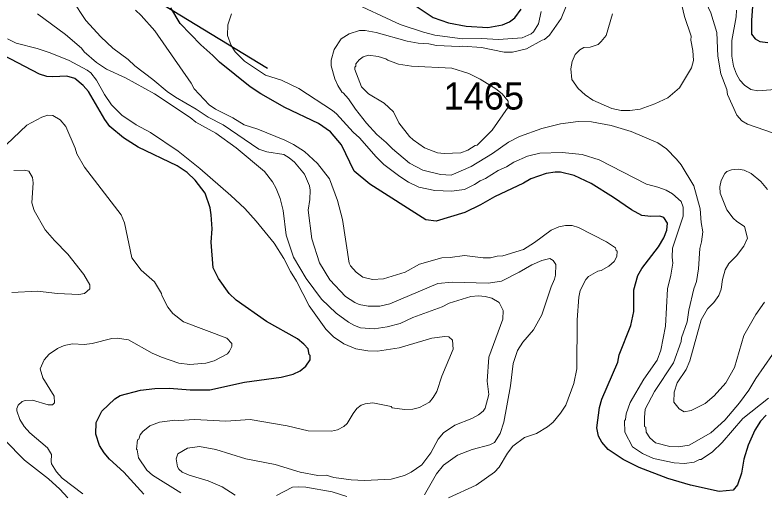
# Model space of a CAD drawing. Extents: x 598.3 to 623.2, y 6902.2 to 6930.1.
# Drawn here: x 600.922 to 603.134, y 6910.701 to 6912.11 of the extents above; entities that cross this region are included whole.
import ezdxf

# ---------------------------------------------------------------- set-up
doc = ezdxf.new("R2010")
doc.units = 0
doc.header["$LTSCALE"] = 0.032
for name, color, linetype, lineweight in [('1', 7, 'Continuous', 25), ('2', 7, 'Continuous', 13), ('26', 7, 'Continuous', 25)]:
    doc.layers.add(name, color=color, linetype=linetype, lineweight=lineweight)
doc.layers.add('21', color=7, linetype='Continuous')

msp = doc.modelspace()

# ---------------------------------------------------------------- linework, layer by layer
at = {"layer": '1'}
for points in [[(603.1021, 6912.1642), (603.0971, 6912.0933), (603.0969, 6912.0536), (603.1081, 6912.0394), (603.1219, 6912.0314), (603.145, 6912.0283)], [(602.1071, 6912.1361), (602.1574, 6912.1028), (602.202, 6912.0865), (602.2546, 6912.0774), (602.3188, 6912.0728), (602.3613, 6912.0811), (602.382, 6912.0899), (602.3984, 6912.1017), (602.4173, 6912.1272)], [(601.4101, 6912.085), (601.3825, 6912.1309)], [(603.1408, 6910.9279), (603.1241, 6910.9102), (603.1069, 6910.8834), (603.0874, 6910.8396), (603.0747, 6910.7981), (603.0675, 6910.7564), (603.056, 6910.7225), (603.0429, 6910.7063), (603.0015, 6910.7023), (602.9173, 6910.7209), (602.8505, 6910.7406), (602.7656, 6910.7733), (602.7178, 6910.7973), (602.6737, 6910.8264), (602.6552, 6910.8482), (602.6452, 6910.8665), (602.6408, 6910.8907), (602.6481, 6910.9506), (602.6552, 6910.9755), (602.7023, 6911.0846), (602.7066, 6911.1061), (602.7412, 6911.1931), (602.7492, 6911.2346), (602.7493, 6911.2983), (602.7615, 6911.3404), (602.7729, 6911.3615), (602.8223, 6911.4252), (602.8383, 6911.4521), (602.8471, 6911.4745), (602.8486, 6911.4955), (602.8379, 6911.5118), (602.8261, 6911.5158), (602.8001, 6911.515), (602.7732, 6911.5179), (602.7424, 6911.5344), (602.6894, 6911.5713), (602.6237, 6911.6125), (602.5736, 6911.6359), (602.5326, 6911.6461), (602.5177, 6911.6462), (602.4905, 6911.6421), (602.4451, 6911.626), (602.4236, 6911.6136), (602.3383, 6911.5734), (602.2968, 6911.5494), (602.2508, 6911.5266), (602.1655, 6911.5014), (602.1348, 6911.5053), (601.9703, 6911.6099), (601.9234, 6911.6488), (601.8857, 6911.7268), (601.8537, 6911.7653), (601.818, 6911.7896), (601.7187, 6911.8363), (601.6475, 6911.8769), (601.616, 6911.8983), (601.5259, 6911.9702), (601.506, 6911.9907), (601.4705, 6912.0215), (601.4101, 6912.085)], [(601.5074, 6911.3632), (601.501, 6911.4386), (601.5042, 6911.478), (601.5017, 6911.5201), (601.4979, 6911.5402), (601.4831, 6911.5833), (601.4542, 6911.6217), (601.43, 6911.6451), (601.4011, 6911.6649), (601.2859, 6911.7197), (601.2425, 6911.7467), (601.2017, 6911.7803), (601.1869, 6911.8015), (601.1385, 6911.8839), (601.1227, 6911.9021), (601.0981, 6911.9227), (601.0752, 6911.9294), (601.0338, 6911.9272), (601.0156, 6911.9286), (600.9945, 6911.935), (600.8872, 6911.9911)], [(601.3022, 6910.6944), (601.2433, 6910.7599), (601.2011, 6910.7981), (601.1848, 6910.817), (601.1717, 6910.838), (601.161, 6910.8716), (601.1611, 6910.9062), (601.1787, 6910.9399), (601.2162, 6910.9761), (601.2325, 6910.9857), (601.2928, 6911.0019), (601.3349, 6911.0067), (601.3777, 6911.0074), (601.4388, 6911.0031), (601.4974, 6911.0025), (601.5994, 6911.0252), (601.7082, 6911.0402), (601.7431, 6911.0493), (601.7637, 6911.0591), (601.7804, 6911.0725), (601.7932, 6911.0911), (601.794, 6911.1039), (601.7907, 6911.1068), (601.7875, 6911.1238), (601.7752, 6911.1379), (601.7564, 6911.1533), (601.6651, 6911.2051), (601.5754, 6911.2681), (601.5547, 6911.2874), (601.5228, 6911.332), (601.5074, 6911.3632)]]:
    msp.add_lwpolyline(points, dxfattribs=at)
at = {"layer": '2'}
for points in [[(603.1877, 6911.7517), (603.0854, 6911.7872), (603.0683, 6911.7972), (603.0538, 6911.8145), (603.0261, 6911.8755), (603.0245, 6911.8904), (603.0066, 6911.9359), (602.9976, 6911.9887), (602.9952, 6912.0587), (602.9772, 6912.1162), (602.9552, 6912.1633), (602.9523, 6912.1837), (602.9377, 6912.226), (602.925, 6912.2514), (602.9032, 6912.2809), (602.8854, 6912.3113), (602.8346, 6912.3743), (602.7973, 6912.427)], [(602.0294, 6911.2572), (601.999, 6911.2497), (601.9651, 6911.2495), (601.9387, 6911.2553), (601.9254, 6911.2606), (601.8984, 6911.2786), (601.8522, 6911.328), (601.8215, 6911.3777), (601.7989, 6911.4484), (601.7876, 6911.5331), (601.7923, 6911.565), (601.7933, 6911.5927), (601.7915, 6911.6059), (601.7772, 6911.6394), (601.7472, 6911.675), (601.7312, 6911.6886), (601.7157, 6911.6981), (601.6655, 6911.7058), (601.6421, 6911.714), (601.5369, 6911.786), (601.4919, 6911.8085), (601.4573, 6911.8322), (601.3958, 6911.8672), (601.3711, 6911.8844), (601.3292, 6911.9199), (601.2757, 6911.9603), (601.2556, 6911.9788), (601.211, 6912.0122), (601.1749, 6912.0458), (601.1306, 6912.0941), (601.0905, 6912.1561)], [(602.55, 6912.1356), (602.5354, 6912.0992), (602.501, 6912.0505), (602.4854, 6912.0376), (602.4786, 6912.0361), (602.4322, 6912.0104), (602.3917, 6912.0007), (602.3666, 6912.0007), (602.2994, 6912.0136), (602.2431, 6912.0183), (602.2335, 6912.0169), (602.1671, 6912.0201), (602.144, 6912.0249), (602.1122, 6912.0272), (602.0798, 6912.0328), (601.9886, 6912.0581), (601.9559, 6912.0638), (601.9393, 6912.0638), (601.9086, 6912.0543), (601.8855, 6912.0393), (601.8643, 6912.0083), (601.8556, 6911.9767), (601.8556, 6911.96), (601.8662, 6911.9214), (601.8751, 6911.9017), (601.8883, 6911.8807), (601.8914, 6911.8797), (601.9065, 6911.8622), (601.9271, 6911.8319), (601.9598, 6911.7904), (601.9907, 6911.7571), (602.018, 6911.7337), (602.0366, 6911.7143), (602.087, 6911.6719), (602.1261, 6911.6516), (602.1788, 6911.6389), (602.2105, 6911.6374), (602.2695, 6911.6629), (602.3326, 6911.7008), (602.3792, 6911.7343), (602.4117, 6911.7509), (602.4775, 6911.7749), (602.5326, 6911.7886), (602.5855, 6911.7958), (602.6248, 6911.7942), (602.6826, 6911.7838), (602.7418, 6911.7663), (602.8207, 6911.7326), (602.8465, 6911.7148), (602.8761, 6911.6843), (602.8891, 6911.6674), (602.9271, 6911.6059), (602.9451, 6911.5376), (602.9483, 6911.4972), (602.9531, 6911.4694), (602.9499, 6911.4405), (602.945, 6911.4202), (602.9411, 6911.3601), (602.9346, 6911.3226), (602.9266, 6911.3007), (602.912, 6911.2384), (602.907, 6911.2042), (602.8902, 6911.1562), (602.8899, 6911.1456), (602.8666, 6911.083)], [(601.9071, 6912.1529), (602.0598, 6912.0815), (602.1281, 6912.0588), (602.1615, 6912.0509), (602.2436, 6912.0396), (602.2997, 6912.0403), (602.3503, 6912.0379), (602.4196, 6912.0425), (602.4462, 6912.0539), (602.4533, 6912.0601), (602.4676, 6912.0838), (602.4756, 6912.1205)], [(602.8886, 6912.1523), (602.8993, 6912.1058), (602.9191, 6912.0476), (602.9184, 6912.0361), (602.924, 6912.0055), (602.9263, 6911.9759), (602.9195, 6911.9543), (602.885, 6911.8952), (602.8502, 6911.8653), (602.8114, 6911.8472), (602.7686, 6911.8315), (602.7383, 6911.8276), (602.7123, 6911.8282), (602.6843, 6911.8343), (602.6289, 6911.8585), (602.6062, 6911.8739), (602.5851, 6911.8928), (602.5663, 6911.9199), (602.5639, 6911.9511), (602.567, 6911.9728), (602.5766, 6911.9935), (602.5898, 6912.0071), (602.6022, 6912.0136), (602.6204, 6912.015), (602.6438, 6912.0232), (602.6536, 6912.0314), (602.6681, 6912.049), (602.6868, 6912.1134)], [(601.9537, 6910.7347), (602.0327, 6910.7393), (602.0723, 6910.75), (602.0924, 6910.76), (602.1235, 6910.7817), (602.1503, 6910.8167), (602.1719, 6910.8575), (602.187, 6910.8759), (602.2208, 6910.899), (602.2713, 6910.9183), (602.2908, 6910.9288), (602.3042, 6910.9396), (602.3104, 6910.9492), (602.3209, 6910.9888), (602.3169, 6911.0282), (602.3209, 6911.0995), (602.3631, 6911.2112), (602.3638, 6911.237), (602.352, 6911.2605), (602.3305, 6911.2734), (602.3105, 6911.2786), (602.2906, 6911.2803), (602.2685, 6911.2786), (602.2046, 6911.2587), (602.184, 6911.2477), (602.0967, 6911.217), (602.0593, 6911.1991), (602.0214, 6911.1893), (601.9824, 6911.1831), (601.9427, 6911.1864), (601.9241, 6911.1926), (601.9064, 6911.2026), (601.8706, 6911.229), (601.8274, 6911.2703), (601.7814, 6911.3315), (601.7448, 6911.395), (601.7228, 6911.4597), (601.7139, 6911.5323), (601.705, 6911.5682), (601.6935, 6911.5978), (601.6825, 6911.6168), (601.659, 6911.6475), (601.5748, 6911.718), (601.515, 6911.7609), (601.4561, 6911.7939), (601.4392, 6911.8074), (601.3342, 6911.8768), (601.2479, 6911.9244), (601.1922, 6911.9502), (601.1621, 6911.9695), (601.1261, 6912.0016), (601.1178, 6912.0122), (601.0709, 6912.0526), (600.9883, 6912.1136)], [(602.2018, 6910.6843), (602.2843, 6910.7215), (602.3384, 6910.7593), (602.3519, 6910.7743), (602.3767, 6910.8154), (602.3925, 6910.8368), (602.4268, 6910.8624), (602.4624, 6910.8737), (602.4946, 6910.8938), (602.5116, 6910.9075), (602.5329, 6910.9336), (602.5483, 6910.9578), (602.5721, 6911.0218), (602.5808, 6911.0649), (602.5825, 6911.2099), (602.5872, 6911.2761), (602.5912, 6911.2959), (602.608, 6911.329), (602.6155, 6911.3376), (602.6436, 6911.3532), (602.6536, 6911.3556), (602.6756, 6911.3686), (602.692, 6911.3817), (602.699, 6911.3966), (602.7006, 6911.4127), (602.6974, 6911.4148), (602.6952, 6911.4223), (602.6685, 6911.4404), (602.586, 6911.4824), (602.5679, 6911.4882), (602.5482, 6911.4882), (602.5281, 6911.484), (602.5052, 6911.4748), (602.4558, 6911.4377), (602.4233, 6911.4176), (602.3626, 6911.3985), (602.3459, 6911.3976), (602.3263, 6911.3931), (602.3051, 6911.3928), (602.2493, 6911.4001), (602.2074, 6911.3936), (602.1824, 6911.3927), (602.1163, 6911.3741), (602.0738, 6911.3506), (602.0106, 6911.3312), (601.9781, 6911.3288), (601.9489, 6911.3355), (601.9299, 6911.35), (601.9132, 6911.369), (601.9093, 6911.3766), (601.8895, 6911.5061), (601.8742, 6911.5617), (601.8503, 6911.6257), (601.8154, 6911.6717), (601.777, 6911.707), (601.7441, 6911.7277), (601.7187, 6911.7404), (601.6395, 6911.7729), (601.5986, 6911.7859), (601.5652, 6911.8058), (601.514, 6911.8316), (601.4953, 6911.8444), (601.4513, 6911.8915), (601.4423, 6911.909), (601.3346, 6912.0634), (601.2947, 6912.1081), (601.2773, 6912.1239)], [(602.7867, 6911.6103), (602.647, 6911.6826), (602.5968, 6911.698), (602.5377, 6911.7043), (602.4724, 6911.7019), (602.4351, 6911.693), (602.3951, 6911.6755), (602.3737, 6911.6617), (602.3491, 6911.6508), (602.3119, 6911.6274), (602.2957, 6911.6201), (602.2793, 6911.6089), (602.2492, 6911.5944), (602.2107, 6911.5895), (602.1618, 6911.5918), (602.1143, 6911.6011), (602.0841, 6911.616), (602.058, 6911.6325), (602.0117, 6911.6683), (601.989, 6911.6906), (601.9393, 6911.747), (601.9202, 6911.7636), (601.8711, 6911.8183), (601.8598, 6911.8281), (601.7603, 6911.8929), (601.7091, 6911.9178), (601.6618, 6911.9324), (601.5994, 6911.9735), (601.5721, 6912.0009), (601.5602, 6912.0202), (601.5496, 6912.0492), (601.5502, 6912.0807), (601.5609, 6912.1139)], [(603.0527, 6912.124), (603.052, 6912.1046), (603.0391, 6912.0351), (603.0391, 6911.9888), (603.0442, 6911.9593), (603.0533, 6911.9348), (603.0628, 6911.9177)], [(600.8993, 6912.0392), (600.925, 6912.0265), (600.9872, 6912.0114), (601.0257, 6911.9986), (601.0822, 6911.9753), (601.1349, 6911.9466), (601.1453, 6911.9387), (601.1628, 6911.9179), (601.1863, 6911.8753), (601.2065, 6911.845), (601.2369, 6911.8138), (601.2795, 6911.786), (601.3216, 6911.7634), (601.4036, 6911.7078), (601.4675, 6911.657), (601.5597, 6911.5769), (601.6004, 6911.5385), (601.6344, 6911.5015), (601.6871, 6911.4364), (601.7162, 6911.3906), (601.7353, 6911.3527), (601.7534, 6911.3242), (601.7906, 6911.2514), (601.8399, 6911.1817), (601.8624, 6911.1596), (601.8931, 6911.1392), (601.9286, 6911.1243), (601.9638, 6911.1177), (601.9922, 6911.1168), (602.0566, 6911.1265), (602.1529, 6911.1557), (602.1918, 6911.1604), (602.2033, 6911.1596), (602.2141, 6911.1495), (602.2164, 6911.123), (602.1828, 6911.0428)], [(603.0628, 6911.9177), (603.0768, 6911.9029), (603.095, 6911.8898), (603.1158, 6911.8858), (603.1669, 6911.8898)], [(601.2231, 6911.1555), (601.2568, 6911.1506), (601.3272, 6911.1113), (601.3547, 6911.0994), (601.406, 6911.0821), (601.4385, 6911.0779), (601.4851, 6911.0812), (601.51, 6911.0887), (601.5495, 6911.1095), (601.5557, 6911.1167), (601.5624, 6911.1313), (601.5622, 6911.1396), (601.5475, 6911.1557), (601.4195, 6911.2036), (601.3881, 6911.228), (601.3735, 6911.2467), (601.3553, 6911.2813), (601.3548, 6911.2873), (601.3342, 6911.3223), (601.2949, 6911.3568), (601.2666, 6911.3931), (601.2451, 6911.4958), (601.2349, 6911.5193), (601.1271, 6911.6605), (601.1047, 6911.7003), (601.0998, 6911.7165), (601.0719, 6911.7805), (601.0556, 6911.8), (601.034, 6911.8133), (601.0189, 6911.8137), (601.0009, 6911.8081), (600.9571, 6911.7845), (600.8347, 6911.669)], [(600.9181, 6911.6509), (600.9501, 6911.6518), (600.9625, 6911.6492), (600.9732, 6911.6302), (600.9756, 6911.614), (600.9715, 6911.5552), (600.9782, 6911.5326), (601.0114, 6911.4751), (601.0381, 6911.4435), (601.0778, 6911.4039), (601.1255, 6911.3439), (601.143, 6911.3134), (601.1431, 6911.3015), (601.1271, 6911.2872), (601.1105, 6911.2843), (601.0472, 6911.2876), (600.9883, 6911.294), (600.9123, 6911.2908)], [(603.1442, 6911.5949), (603.1247, 6911.6187), (603.0963, 6911.6414), (603.0753, 6911.6513), (603.0574, 6911.655), (603.0377, 6911.6526), (603.0242, 6911.6473), (603.0181, 6911.6419), (603.0073, 6911.6213), (603.0034, 6911.6027), (603.005, 6911.5833), (603.0242, 6911.535), (603.043, 6911.5101), (603.0541, 6911.4998), (603.0769, 6911.485), (603.0851, 6911.4513), (603.075, 6911.427), (603.0525, 6911.3982), (603.0305, 6911.3762), (603.019, 6911.3569), (603.0115, 6911.3291), (603.0075, 6911.2999), (603.0008, 6911.2817), (602.9855, 6911.2609), (602.9677, 6911.2422), (602.9486, 6911.2096), (602.9149, 6911.0887), (602.9045, 6911.0631), (602.878, 6911.0234), (602.8692, 6910.9959), (602.8674, 6910.9664), (602.8838, 6910.9465), (602.8982, 6910.9379), (602.919, 6910.9417), (602.9603, 6910.9628), (602.9866, 6910.9849), (603.0216, 6911.0239), (603.0474, 6911.0691), (603.0744, 6911.1631), (603.1102, 6911.2252), (603.136, 6911.2622)], [(603.147, 6910.9778), (603.0717, 6910.9185), (603.0104, 6910.8477), (602.9819, 6910.82), (602.9488, 6910.797), (602.9432, 6910.7968), (602.9276, 6910.7897), (602.8991, 6910.7857), (602.869, 6910.7872), (602.8078, 6910.7998), (602.7748, 6910.8152), (602.7457, 6910.8348), (602.7233, 6910.8774), (602.7216, 6910.9117), (602.7249, 6910.9155), (602.727, 6910.9318), (602.7389, 6910.9651), (602.7791, 6911.0348), (602.8188, 6911.0908), (602.8294, 6911.1202), (602.8431, 6911.1912), (602.8487, 6911.3013), (602.8591, 6911.3412), (602.8649, 6911.3774), (602.8626, 6911.3943), (602.8634, 6911.4215), (602.8958, 6911.5156), (602.8957, 6911.5425), (602.8892, 6911.5587), (602.8637, 6911.5817), (602.8453, 6911.5924), (602.8202, 6911.6017), (602.7867, 6911.6103)], [(602.1309, 6910.6928), (602.1672, 6910.7549), (602.1877, 6910.7801), (602.229, 6910.8096), (602.2722, 6910.8271), (602.3239, 6910.84), (602.3385, 6910.8477), (602.3549, 6910.8739), (602.3655, 6910.9077), (602.3857, 6911.0145), (602.3937, 6911.0802), (602.4059, 6911.1188), (602.4214, 6911.144), (602.4531, 6911.1801), (602.4776, 6911.2246), (602.5052, 6911.3067), (602.5157, 6911.3294), (602.5185, 6911.3415), (602.5193, 6911.373), (602.5112, 6911.3845), (602.5011, 6911.3904), (602.4782, 6911.385), (602.4479, 6911.3716), (602.4114, 6911.3501), (602.3587, 6911.3239), (602.3191, 6911.3175), (602.2127, 6911.3208), (602.1712, 6911.3166), (602.0294, 6911.2572)], [(601.1225, 6910.6961), (601.0614, 6910.7419), (601.0444, 6910.7605), (601.0299, 6910.7847), (601.0283, 6910.7911), (601.0298, 6910.8115), (601.0181, 6910.8314), (600.9654, 6910.8761), (600.9487, 6910.8941), (600.9357, 6910.9149), (600.9271, 6910.9413), (600.9271, 6910.9475), (600.9316, 6910.9575), (600.9429, 6910.9684), (600.9517, 6910.9712), (600.9732, 6910.9726), (601.0201, 6910.9581), (601.0328, 6910.9589), (601.038, 6910.9643), (601.0379, 6910.9837), (601.0044, 6911.0381), (600.9959, 6911.0649), (601.0083, 6911.0916), (601.0229, 6911.1082), (601.0475, 6911.1247), (601.0671, 6911.1337), (601.0914, 6911.1385), (601.126, 6911.137), (601.1494, 6911.1401), (601.2077, 6911.1541), (601.2231, 6911.1555)], [(602.8666, 6911.083), (602.8106, 6910.9983), (602.783, 6910.9458), (602.7807, 6910.9214), (602.7816, 6910.8944), (602.7848, 6910.8923), (602.7865, 6910.8774), (602.7968, 6910.8615), (602.8133, 6910.8464), (602.8555, 6910.8351), (602.8813, 6910.8343), (602.9131, 6910.8397), (602.9775, 6910.8754), (603.0185, 6910.9133), (603.0615, 6910.9643), (603.0897, 6911.0019), (603.1097, 6911.0366), (603.159, 6911.1073)], [(602.1828, 6911.0428), (602.1676, 6910.998), (602.1574, 6910.9802), (602.1459, 6910.966), (602.1168, 6910.9504), (602.0968, 6910.9461), (602.0719, 6910.9451), (602.0355, 6910.95), (602.0331, 6910.9532), (601.9789, 6910.9645), (601.9562, 6910.9613), (601.9445, 6910.9571), (601.9319, 6910.9478), (601.9204, 6910.9333), (601.9034, 6910.9033), (601.8934, 6910.8947), (601.8747, 6910.885), (601.8563, 6910.8804), (601.7874, 6910.8821), (601.7258, 6910.8966), (601.6162, 6910.9151), (601.5441, 6910.9104), (601.4515, 6910.9152), (601.406, 6910.912), (601.3939, 6910.9135), (601.3488, 6910.907), (601.3197, 6910.8965), (601.2998, 6910.8798), (601.2914, 6910.8698), (601.2873, 6910.8574), (601.2841, 6910.8551), (601.2808, 6910.828), (601.283, 6910.8255), (601.2867, 6910.8021), (601.3109, 6910.7652), (601.3283, 6910.7504), (601.4119, 6910.6982)], [(600.8904, 6910.8553), (600.9495, 6910.7947), (601.0203, 6910.7402), (601.0546, 6910.7091), (601.0782, 6910.6837)], [(601.572, 6910.6919), (601.5333, 6910.7168), (601.492, 6910.7342), (601.436, 6910.7504), (601.4157, 6910.76), (601.4053, 6910.769), (601.4022, 6910.7754), (601.3982, 6910.7994), (601.4023, 6910.8139), (601.4313, 6910.8309), (601.4669, 6910.8359), (601.5153, 6910.8262), (601.6039, 6910.7992), (601.6902, 6910.7825), (601.7641, 6910.7595), (601.8167, 6910.7501), (601.8409, 6910.7508), (601.8639, 6910.7435), (601.9148, 6910.7369), (601.9537, 6910.7347)], [(601.6939, 6910.691), (601.7415, 6910.7152), (601.7595, 6910.7168), (601.781, 6910.7152), (601.8583, 6910.7016), (601.9023, 6910.6874)]]:
    msp.add_lwpolyline(points, dxfattribs=at)
msp.add_lwpolyline([(602.0176, 6911.981), (602.0228, 6911.977), (602.0547, 6911.9651), (602.093, 6911.9586), (602.2117, 6911.9529), (602.2625, 6911.9373), (602.2962, 6911.9204), (602.3418, 6911.8918), (602.3612, 6911.877), (602.3782, 6911.8553), (602.3783, 6911.8379), (602.3313, 6911.7702), (602.2872, 6911.7257), (602.2808, 6911.7246), (602.2592, 6911.7111), (602.239, 6911.7027), (602.1897, 6911.7012), (602.1699, 6911.7027), (602.131, 6911.718), (602.0981, 6911.741), (602.0874, 6911.751), (602.0551, 6911.7917), (602.0395, 6911.8237), (602.0124, 6911.8494), (601.9659, 6911.8772), (601.9452, 6911.8976), (601.9252, 6911.9487), (601.9252, 6911.9558), (601.9283, 6911.9589), (601.929, 6911.9654), (601.9382, 6911.9772), (601.9499, 6911.9864), (601.9657, 6911.9909), (601.9946, 6911.9878)], close=True, dxfattribs=at)
at = {"layer": '26'}
msp.add_lwpolyline([(599.0555, 6913.6532), (599.6413, 6913.1902), (600.4019, 6912.68), (600.9641, 6912.3824), (601.668, 6911.9525)], dxfattribs=at)

# ---------------------------------------------------------------- texts
at = {"layer": '21'}
msp.add_text('1465', height=0.08, dxfattribs=at).set_placement((602.1874, 6911.8307))

doc.saveas('drawing.dxf')
